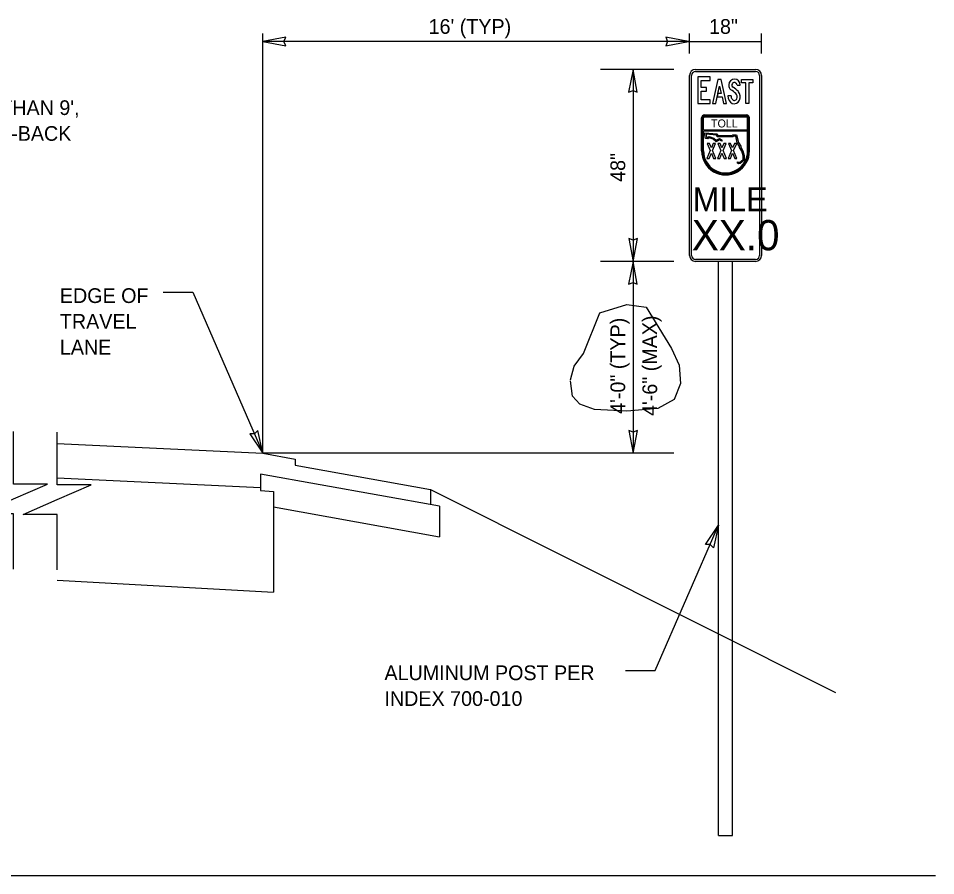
# Model space of a CAD drawing. Extents: x 57428 to 58066, y 11696 to 12105.
# Drawn here: x 57891.5 to 58065.9, y 11934.3 to 12097.3 of the extents above; entities that cross this region are included whole.
import ezdxf

# ---------------------------------------------------------------- set-up
doc = ezdxf.new("R2010")
doc.units = 0
for name, color, linetype in [('52', 7, 'Continuous'), ('62', 7, 'Continuous'), ('Default', 7, 'Continuous'), ('DimLines_dp', 7, 'Continuous'), ('NonPlottingEle_dp', 7, 'Continuous'), ('SignPanel', 7, 'Continuous'), ('TextMisc', 7, 'Continuous'), ('XSGrdLine_ex', 7, 'Continuous')]:
    doc.layers.add(name, color=color, linetype=linetype)

msp = doc.modelspace()

# ---------------------------------------------------------------- linework, layer by layer
at = {"layer": '52'}
msp.add_line((58016.11, 12014.58), (57937.99, 12014.58), dxfattribs=at)
at = {"layer": '62'}
msp.add_lwpolyline([(57996.45, 12028.52), (57997.15, 12031.12), (57998.95, 12033.52), (58002.06, 12041.28), (58007.16, 12042.88), (58010.86, 12042.38), (58015.66, 12034.52), (58017.16, 12031.32), (58017.36, 12027.82), (58016.16, 12024.81), (58013.06, 12023.11), (58007.16, 12022.61), (58001.05, 12022.91), (57998.25, 12023.91), (57996.85, 12025.41), (57996.45, 12028.32)], dxfattribs=at)
at = {"layer": 'Default'}
for points in [[(57890.6, 11992.52), (57890.6, 12003.08), (57884.14, 12003.08), (57890.6, 12005.89), (57897.06, 12008.71), (57890.6, 12008.71), (57890.6, 12018.71)], [(57898.9, 11992.39), (57898.9, 12002.95), (57892.44, 12002.95), (57898.9, 12005.76), (57905.36, 12008.57), (57898.9, 12008.57), (57898.9, 12018.57)]]:
    msp.add_lwpolyline(points, dxfattribs=at)
at = {"layer": 'DimLines_dp'}
for p, q in [((57937.99, 12014.58), (57937.99, 12094.4)), ((57942.34, 12093.67), (57937.99, 12092.86)), ((58019.11, 12092.86), (57937.99, 12092.86)), ((57937.99, 12092.86), (57942.34, 12092.02)), ((57942.01, 12092.86), (57942.34, 12093.67)), ((57942.34, 12092.02), (57942.01, 12092.86)), ((58018.92, 12092.86), (58014.57, 12093.7)), ((58014.57, 12093.7), (58014.9, 12092.86)), ((58014.9, 12092.86), (58014.57, 12092.05)), ((58014.57, 12092.05), (58018.92, 12092.86)), ((58019.11, 12090.57), (58019.11, 12094.4)), ((58019.11, 12092.86), (58032.79, 12092.86)), ((58032.79, 12090.57), (58032.79, 12094.4)), ((58016.11, 12087.57), (58002.18, 12087.57)), ((58008.36, 12087.57), (58007.52, 12083.22)), ((58008.36, 12087.57), (58008.36, 12051.07)), ((58009.17, 12083.22), (58008.36, 12087.57)), ((58007.52, 12083.22), (58008.36, 12083.55)), ((58008.36, 12083.55), (58009.17, 12083.22)), ((58008.36, 12055.09), (58007.55, 12055.42)), ((58007.55, 12055.42), (58008.36, 12051.07)), ((58008.36, 12055.09), (58007.55, 12055.42)), ((58007.55, 12055.42), (58008.36, 12051.07)), ((58008.36, 12051.07), (58009.2, 12055.42)), ((58009.2, 12055.42), (58008.36, 12055.09)), ((58008.36, 12051.07), (58009.2, 12055.42)), ((58009.2, 12055.42), (58008.36, 12055.09)), ((58016.11, 12051.07), (58002.18, 12051.07)), ((58008.36, 12051.07), (58007.52, 12046.72)), ((58008.36, 12051.07), (58008.36, 12014.58)), ((58009.17, 12046.72), (58008.36, 12051.07)), ((58007.52, 12046.72), (58008.36, 12047.05)), ((58008.36, 12047.05), (58009.17, 12046.72)), ((57919.02, 12045.19), (57924.67, 12045.19)), ((57924.67, 12045.19), (57937.99, 12014.57)), ((57936.38, 12018.26), (57935.51, 12018.24)), ((57935.51, 12018.24), (57937.99, 12014.57)), ((57937.02, 12018.9), (57936.38, 12018.26)), ((57937.99, 12014.57), (57937.02, 12018.9)), ((58008.36, 12018.6), (58007.55, 12018.93)), ((58007.55, 12018.93), (58008.36, 12014.58)), ((58008.36, 12014.58), (58009.2, 12018.93)), ((58009.2, 12018.93), (58008.36, 12018.6)), ((58012.58, 11973.24), (58024.62, 12000.91)), ((58022.14, 11997.25), (58024.62, 12000.91)), ((58024.62, 12000.91), (58023.65, 11996.59)), ((58023.01, 11997.23), (58022.14, 11997.25)), ((58023.65, 11996.59), (58023.01, 11997.23)), ((58006.93, 11973.24), (58012.58, 11973.24))]:
    msp.add_line(p, q, dxfattribs=at)
at = {"layer": 'NonPlottingEle_dp'}
for p, q in [((58024.62, 11980.19), (58024.62, 12051.07)), ((58027.28, 11978.86), (58027.28, 12051.07)), ((58024.62, 11941.87), (58024.62, 11980.19)), ((58027.28, 11941.87), (58027.28, 11978.86)), ((58024.62, 11941.87), (58027.28, 11941.87))]:
    msp.add_line(p, q, dxfattribs=at)
at = {"layer": 'SignPanel'}
for p, q in [((58028.14, 12084.57), (58028.73, 12084.57)), ((58028.14, 12084.57), (58028.73, 12084.57)), ((58028.14, 12084.57), (58028.73, 12084.57)), ((58027.01, 12082.53), (58026.41, 12082.53)), ((58027.01, 12082.53), (58026.41, 12082.53)), ((58027.01, 12082.53), (58026.41, 12082.53)), ((58021.96, 12078.91), (58029.94, 12078.91)), ((58021.39, 12072.06), (58021.39, 12078.34)), ((58021.58, 12072.06), (58021.58, 12078.34)), ((58021.77, 12076.05), (58021.77, 12078.34)), ((58021.96, 12078.71), (58029.94, 12078.71)), ((58021.96, 12078.52), (58029.94, 12078.52)), ((58030.13, 12076.05), (58030.13, 12078.34)), ((58030.32, 12072.06), (58030.32, 12078.34)), ((58030.51, 12072.06), (58030.51, 12078.34)), ((58021.77, 12076.05), (58030.13, 12076.05)), ((58021.77, 12072.06), (58021.77, 12075.86)), ((58021.77, 12075.86), (58030.13, 12075.86)), ((58022.15, 12074.41), (58021.98, 12075.5)), ((58021.98, 12075.5), (58024.36, 12075.31)), ((58024.36, 12075.31), (58024.5, 12074.97)), ((58030.13, 12072.06), (58030.13, 12075.86)), ((58022.61, 12074.35), (58022.15, 12074.41)), ((58024.2, 12075.09), (58022.25, 12075.24)), ((58022.25, 12075.24), (58022.35, 12074.61)), ((58022.35, 12074.61), (58022.54, 12074.59)), ((58022.54, 12074.59), (58022.81, 12074.8)), ((58022.86, 12074.55), (58022.61, 12074.35)), ((58022.81, 12074.8), (58023.73, 12074.5)), ((58023.61, 12074.3), (58022.86, 12074.55)), ((58023.24, 12075.16), (58023.24, 12075.16)), ((58024.15, 12073.8), (58023.61, 12074.3)), ((58023.73, 12074.5), (58024.18, 12074.09)), ((58024.78, 12074.17), (58024.15, 12073.8)), ((58024.18, 12074.09), (58024.79, 12074.45)), ((58024.34, 12074.74), (58024.2, 12075.09)), ((58027.35, 12074.74), (58024.34, 12074.74)), ((58024.5, 12074.97), (58027.23, 12074.97)), ((58025.16, 12073.92), (58024.78, 12074.17)), ((58024.79, 12074.45), (58025.29, 12074.11)), ((58025.29, 12074.11), (58025.16, 12073.92)), ((58027.23, 12074.97), (58027.33, 12075.12)), ((58027.33, 12075.12), (58028.06, 12075.12)), ((58027.45, 12074.89), (58027.35, 12074.74)), ((58027.88, 12074.89), (58027.45, 12074.89)), ((58028.18, 12073.6), (58027.88, 12074.89)), ((58028.06, 12075.12), (58028.4, 12073.69)), ((58028.62, 12072.9), (58028.18, 12073.6)), ((58028.4, 12073.69), (58028.85, 12072.96)), ((58028.62, 12072.72), (58028.62, 12072.9)), ((58029.05, 12072.01), (58028.62, 12072.72)), ((58028.85, 12072.96), (58028.85, 12072.78)), ((58028.85, 12072.78), (58029.26, 12072.11)), ((58029.28, 12071.15), (58029.05, 12072.01)), ((58029.26, 12072.11), (58029.51, 12071.18)), ((58028.65, 12069.92), (58029.28, 12070.43)), ((58029.51, 12070.32), (58028.76, 12069.7)), ((58029.28, 12070.43), (58029.28, 12071.15)), ((58029.51, 12071.18), (58029.51, 12070.32)), ((58028.18, 12069.78), (58028.31, 12069.96)), ((58028.4, 12069.62), (58028.18, 12069.78)), ((58028.31, 12069.96), (58028.45, 12069.87)), ((58028.76, 12069.7), (58028.4, 12069.62)), ((58028.45, 12069.87), (58028.65, 12069.92))]:
    msp.add_line(p, q, dxfattribs=at)
for points in [[(58020.25, 12087.57), (58031.65, 12087.57)], [(58019.11, 12052.21), (58019.11, 12086.43)], [(58019.49, 12052.21), (58019.49, 12086.43)], [(58020.25, 12087.19), (58031.65, 12087.19)], [(58032.41, 12086.43), (58032.41, 12052.21)], [(58032.79, 12086.43), (58032.79, 12052.21)], [(58031.65, 12051.45), (58020.25, 12051.45)], [(58031.65, 12051.07), (58020.25, 12051.07)]]:
    msp.add_lwpolyline(points, dxfattribs=at)
for points in [[(58021.31, 12081.8), (58021.31, 12083.42), (58022.33, 12083.42), (58022.33, 12084.13), (58021.31, 12084.13), (58021.31, 12085.45), (58023.03, 12085.45), (58023.03, 12086.15), (58020.66, 12086.15), (58020.66, 12081.09), (58023.03, 12081.09), (58023.03, 12081.8)], [(58021.31, 12081.8), (58021.31, 12083.42), (58022.33, 12083.42), (58022.33, 12084.13), (58021.31, 12084.13), (58021.31, 12085.45), (58023.03, 12085.45), (58023.03, 12086.15), (58020.66, 12086.15), (58020.66, 12081.09), (58023.03, 12081.09), (58023.03, 12081.8)], [(58021.31, 12081.8), (58021.31, 12083.42), (58022.33, 12083.42), (58022.33, 12084.13), (58021.31, 12084.13), (58021.31, 12085.45), (58023.03, 12085.45), (58023.03, 12086.15), (58020.66, 12086.15), (58020.66, 12081.09), (58023.03, 12081.09), (58023.03, 12081.8)], [(58025.28, 12082.32), (58025.55, 12081.09), (58026.16, 12081.09), (58025.14, 12085.67), (58024.51, 12085.67), (58023.49, 12081.09), (58024.09, 12081.09), (58024.37, 12082.32)], [(58024.51, 12082.96), (58024.37, 12082.32), (58025.28, 12082.32), (58025.55, 12081.09), (58026.16, 12081.09), (58025.14, 12085.67), (58024.51, 12085.67), (58023.49, 12081.09), (58024.09, 12081.09), (58024.82, 12084.36), (58025.14, 12082.96)], [(58024.51, 12082.96), (58024.37, 12082.32), (58025.28, 12082.32), (58025.55, 12081.09), (58026.16, 12081.09), (58025.14, 12085.67), (58024.51, 12085.67), (58023.49, 12081.09), (58024.09, 12081.09), (58024.82, 12084.36), (58025.14, 12082.96)], [(58024.82, 12084.36), (58025.14, 12082.96), (58024.51, 12082.96)], [(58029.79, 12085.03), (58029.01, 12085.03), (58029.01, 12085.67), (58031.16, 12085.67), (58031.16, 12085.03), (58030.38, 12085.03), (58030.38, 12081.09), (58029.79, 12081.09)], [(58029.79, 12085.03), (58029.01, 12085.03), (58029.01, 12085.67), (58031.16, 12085.67), (58031.16, 12085.03), (58030.38, 12085.03), (58030.38, 12081.09), (58029.79, 12081.09)], [(58029.79, 12085.03), (58029.01, 12085.03), (58029.01, 12085.67), (58031.16, 12085.67), (58031.16, 12085.03), (58030.38, 12085.03), (58030.38, 12081.09), (58029.79, 12081.09)], [(58022.84, 12070.64), (58023.25, 12071.62), (58023.66, 12070.64), (58024.08, 12070.64), (58023.46, 12072.13), (58024.03, 12073.49), (58023.61, 12073.49), (58023.25, 12072.64), (58022.89, 12073.49), (58022.46, 12073.49), (58023.03, 12072.13), (58022.41, 12070.64)], [(58024.86, 12070.64), (58025.26, 12071.62), (58025.67, 12070.64), (58026.1, 12070.64), (58025.48, 12072.13), (58026.05, 12073.49), (58025.62, 12073.49), (58025.26, 12072.64), (58024.91, 12073.49), (58024.48, 12073.49), (58025.05, 12072.13), (58024.43, 12070.64)], [(58026.87, 12070.64), (58027.28, 12071.62), (58027.69, 12070.64), (58028.12, 12070.64), (58027.49, 12072.13), (58028.07, 12073.49), (58027.64, 12073.49), (58027.28, 12072.64), (58026.92, 12073.49), (58026.49, 12073.49), (58027.07, 12072.13), (58026.44, 12070.64)]]:
    msp.add_lwpolyline(points, close=True, dxfattribs=at)
for centre, radius, start, end in [((58020.25, 12086.43), 1.14, 90, 180), ((58031.65, 12086.43), 1.14, 0, 90), ((58020.25, 12086.43), 0.76, 90, 180), ((58031.65, 12086.43), 0.76, 0, 90), ((58020.25, 12052.21), 1.14, 180, 270), ((58020.25, 12052.21), 0.76, 180, 270), ((58031.65, 12052.21), 1.14, 270, 360), ((58031.65, 12052.21), 0.76, 270, 360)]:
    msp.add_arc(centre, radius, start, end, dxfattribs=at)
for centre, major_axis, ratio, start_param, end_param in [((58027.64, 12084.54), (0, 1.19), 0.91923, 4.736267, 7.790596), ((58027.64, 12084.54), (0, 1.19), 0.91923, 4.736267, 7.790596), ((58027.64, 12084.54), (0, 1.19), 0.91923, 4.736267, 7.790596), ((58027.53, 12084.57), (0, 1.07), 0.91923, 1.534831, 2.511766), ((58027.53, 12084.57), (0, 1.07), 0.91923, 1.534831, 2.511766), ((58027.53, 12084.57), (0, 1.07), 0.91923, 1.534831, 2.511766), ((58027.57, 12084.59), (0, 0.46), 0.91923, 0.87378, 2.656959), ((58027.57, 12084.59), (0, 0.46), 0.91923, 0.87378, 2.656959), ((58027.57, 12084.59), (0, 0.46), 0.91923, 0.87378, 2.656959), ((58027.63, 12084.52), (0, 0.558), 0.91923, 4.786904, 7.140738), ((58027.63, 12084.52), (0, 0.558), 0.91923, 4.786904, 7.140738), ((58027.63, 12084.52), (0, 0.558), 0.91923, 4.786904, 7.140738), ((58025.43, 12080.34), (0, 4.39), 0.91923, 5.462886, 5.782242), ((58025.43, 12080.34), (0, 4.39), 0.91923, 5.462886, 5.782242), ((58025.43, 12080.34), (0, 4.39), 0.91923, 5.462886, 5.782242), ((58027.79, 12082.46), (0, 1.5), 0.91923, 1.526364, 2.701682), ((58027.79, 12082.46), (0, 1.5), 0.91923, 1.526364, 2.701682), ((58027.79, 12082.46), (0, 1.5), 0.91923, 1.526364, 2.701682), ((58024.92, 12079.64), (0, 4.63), 0.91923, 5.515137, 5.786988), ((58024.92, 12079.64), (0, 4.63), 0.91923, 5.515137, 5.786988), ((58024.92, 12079.64), (0, 4.63), 0.91923, 5.515137, 5.786988), ((58027.84, 12082.48), (0, 0.911), 0.91923, 1.524757, 2.28214), ((58027.84, 12082.48), (0, 0.911), 0.91923, 1.524757, 2.28214), ((58027.84, 12082.48), (0, 0.911), 0.91923, 1.524757, 2.28214), ((58027.44, 12082.34), (0, 0.792), 0.91923, 4.254409, 5.632398), ((58027.44, 12082.34), (0, 0.792), 0.91923, 4.254409, 5.632398), ((58027.44, 12082.34), (0, 0.792), 0.91923, 4.254409, 5.632398), ((58027.45, 12082.34), (0, 1.42), 0.91923, 4.260987, 5.485755), ((58027.45, 12082.34), (0, 1.42), 0.91923, 4.260987, 5.485755), ((58027.45, 12082.34), (0, 1.42), 0.91923, 4.260987, 5.485755), ((58027.6, 12082.27), (0, 1.24), 0.91923, 2.786047, 4.251692), ((58027.6, 12082.27), (0, 1.24), 0.91923, 2.786047, 4.251692), ((58027.6, 12082.27), (0, 1.24), 0.91923, 2.786047, 4.251692), ((58027.62, 12082.26), (0, 0.581), 0.91923, 2.261787, 4.23006), ((58027.62, 12082.26), (0, 0.581), 0.91923, 2.261787, 4.23006), ((58027.62, 12082.26), (0, 0.581), 0.91923, 2.261787, 4.23006), ((58021.96, 12078.33), (0, 0.57), 0.9997, 0, 1.570796), ((58029.94, 12078.33), (0, 0.57), 0.9997, 4.712389, 6.283185), ((58021.96, 12078.33), (0, 0.38), 0.9997, 0, 1.570796), ((58021.96, 12078.33), (0, 0.19), 0.9997, 0, 1.570796), ((58029.94, 12078.33), (0, 0.38), 0.9997, 4.712389, 6.283185), ((58029.94, 12078.33), (0, 0.19), 0.9997, 4.712389, 6.283185), ((58025.95, 12072.06), (0, -4.56), 0.9997, 4.712389, 7.853982), ((58025.95, 12072.06), (0, -4.37), 0.9997, 4.712389, 7.853982), ((58025.95, 12072.06), (0, -4.18), 0.9997, 4.712389, 7.853982)]:
    msp.add_ellipse(centre, major_axis=major_axis, ratio=ratio, start_param=start_param, end_param=end_param, dxfattribs=at)
at = {"layer": 'TextMisc'}
msp.add_line((58065.89, 11934.25), (57709.55, 11934.25), dxfattribs=at)
at = {"layer": 'XSGrdLine_ex'}
for p, q in [((57937.99, 12014.57), (57944.15, 12013.46)), ((57944.15, 12013.46), (57944.15, 12012.29)), ((57944.15, 12012.29), (57969.87, 12007.66)), ((57937.57, 12010.63), (57937.57, 12007.48)), ((57971.57, 12004.51), (57937.57, 12010.63)), ((57937.57, 12007.48), (57940.04, 12007.33)), ((57940.04, 12007.33), (57940.04, 11988.15)), ((57969.87, 12007.66), (57969.87, 12004.82)), ((57940.04, 12004.37), (57971.57, 11998.7)), ((57971.57, 12004.51), (57971.57, 11998.7)), ((57898.9, 11990.43), (57940.04, 11988.15))]:
    msp.add_line(p, q, dxfattribs=at)
for points in [[(57898.9, 12016.43), (57937.99, 12014.57)], [(57898.9, 12009.93), (57937.57, 12008.09)], [(57969.87, 12007.66), (58046.82, 11969.06)]]:
    msp.add_lwpolyline(points, dxfattribs=at)

# ---------------------------------------------------------------- texts
at = {"layer": 'DimLines_dp'}
for s, p in [("16' (TYP)", (57969.5, 12094.33)), ('18"', (58022.81, 12094.33)), ("FOR DISTANCES LESS THAN 9',", (57846.05, 12078.89)), ('MOUNT SIGNS BACK-TO-BACK', (57846.05, 12073.99)), ('EDGE OF ', (57899.41, 12043.15)), ('TRAVEL ', (57899.41, 12038.25)), ('LANE', (57899.41, 12033.35)), ('ALUMINUM POST PER', (57961.11, 11971.43)), ('INDEX 700-010', (57961.11, 11966.53))]:
    msp.add_text(s, height=2.8, dxfattribs=at).set_placement(p)
for s, p in [('48"', (58006.87, 12066.18)), ('4\'-6" (MAX)', (58012.95, 12021.67)), ('4\'-0" (TYP)', (58006.87, 12022.07))]:
    msp.add_text(s, height=2.8, rotation=90, dxfattribs=at).set_placement(p)
at = {"layer": 'SignPanel'}
for s, height, p in [('TOLL', 1.519, (58023.19, 12076.53)), ('MILE', 4.562, (58019.7, 12060.57)), ('XX.0', 5.75, (58019.54, 12053.17))]:
    msp.add_text(s, height=height, rotation=360, dxfattribs=at).set_placement(p)

doc.saveas('drawing.dxf')
